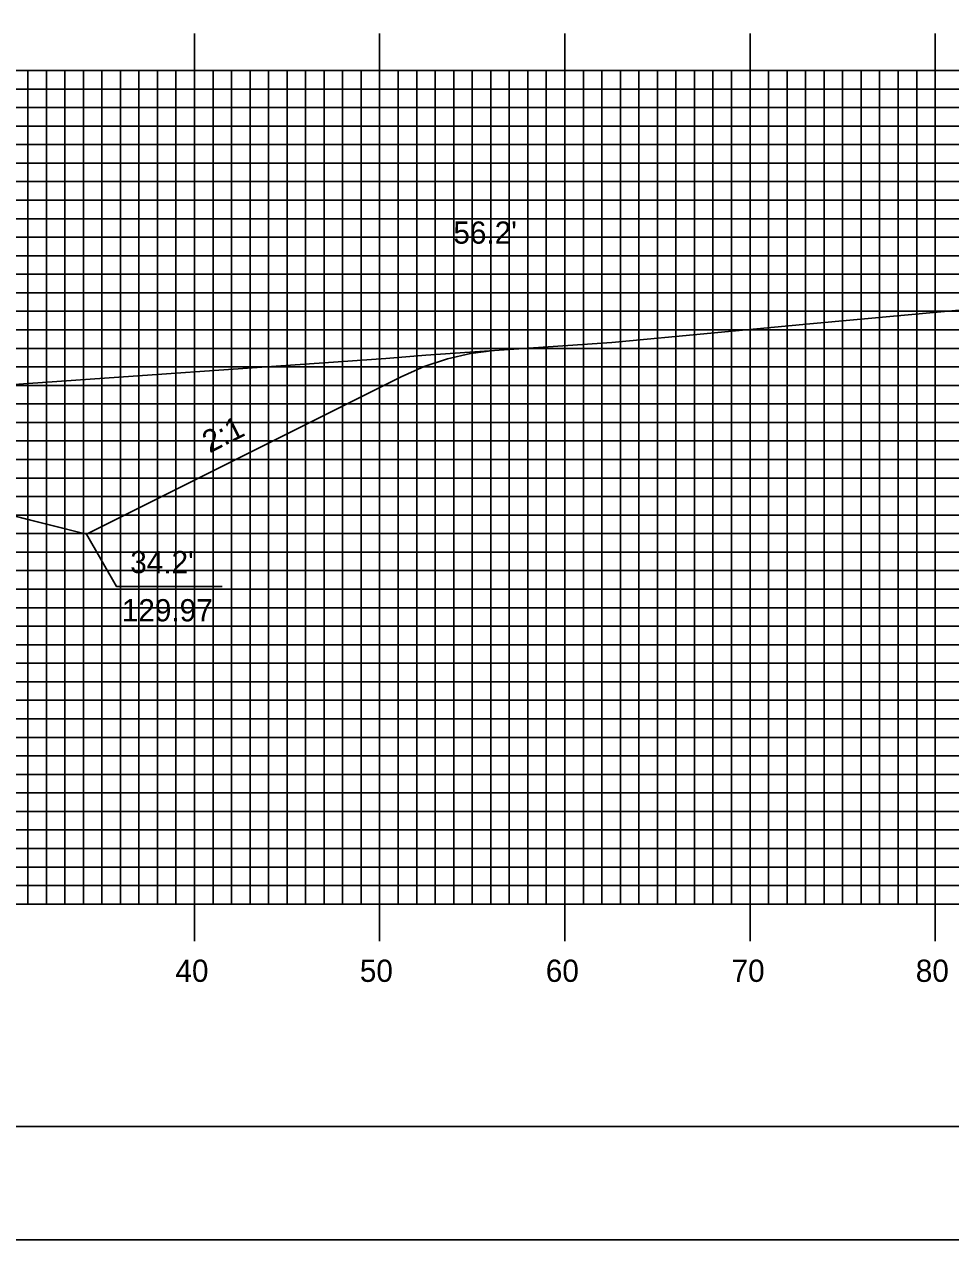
# Model space of a CAD drawing. Extents: x 1782647 to 1782990, y 442591 to 442811.
# Drawn here: x 1782843.8 to 1782893.8, y 442590.5 to 442656.2 of the extents above; entities that cross this region are included whole.
import ezdxf

# ---------------------------------------------------------------- set-up
doc = ezdxf.new("R2010")
doc.units = 0
for name, color, linetype in [('ANNOTATION', 7, 'Continuous'), ('BORDER', 7, 'Continuous'), ('D_Roadway_Centerline', 7, 'Continuous'), ('D_Roadway_SlopeLines', 7, 'Continuous'), ('D_Text_Standard', 7, 'Continuous'), ('H_V ANNOTATION', 7, 'Continuous'), ('MAJOR', 7, 'Continuous'), ('MINOR', 7, 'Continuous'), ('PLOT BOUNDARY', 7, 'Continuous'), ('S_Roadway_Centerline', 7, 'Continuous')]:
    doc.layers.add(name, color=color, linetype=linetype)

msp = doc.modelspace()

# ---------------------------------------------------------------- linework, layer by layer
at = {"layer": 'ANNOTATION'}
msp.add_lwpolyline([(1782854.435, 442625.801), (1782848.743, 442625.801), (1782847.121, 442628.634)], dxfattribs=at)
at = {"layer": 'BORDER'}
msp.add_lwpolyline([(1782663.347, 442596.665), (1782983.347, 442596.665), (1782983.347, 442806.665), (1782663.347, 442806.665)], close=True, dxfattribs=at)
at = {"layer": 'D_Roadway_Centerline'}
msp.add_lwpolyline([(1782771.185, 442630.8), (1782772.435, 442630.887), (1782773.685, 442630.771), (1782774.935, 442630.451), (1782776.185, 442629.928), (1782778.773, 442628.634), (1782782.773, 442629.634), (1782792.947, 442632.178), (1782800.947, 442632.498), (1782812.947, 442632.738), (1782824.947, 442632.498), (1782832.947, 442632.178), (1782843.121, 442629.634), (1782847.121, 442628.634), (1782864.105, 442637.126), (1782865.355, 442637.684), (1782866.605, 442638.106), (1782867.855, 442638.394), (1782869.105, 442638.546)], dxfattribs=at)
at = {"layer": 'D_Roadway_SlopeLines'}
for points in [[(1782847.121, 442628.634), (1782864.105, 442637.126), (1782865.355, 442637.684), (1782866.605, 442638.106), (1782867.855, 442638.394), (1782869.105, 442638.546)], [(1782832.947, 442632.178), (1782847.121, 442628.634)]]:
    msp.add_lwpolyline(points, dxfattribs=at)
at = {"layer": 'MAJOR'}
for p, q in [((1782852.947, 442655.669), (1782852.947, 442653.665)), ((1782862.947, 442655.669), (1782862.947, 442653.665)), ((1782872.947, 442655.669), (1782872.947, 442653.665)), ((1782882.947, 442655.669), (1782882.947, 442653.665)), ((1782892.947, 442655.669), (1782892.947, 442653.665)), ((1782672.947, 442653.665), (1782952.947, 442653.665)), ((1782672.947, 442653.665), (1782952.947, 442653.665)), ((1782852.947, 442608.665), (1782852.947, 442653.665)), ((1782862.947, 442608.665), (1782862.947, 442653.665)), ((1782872.947, 442608.665), (1782872.947, 442653.665)), ((1782882.947, 442608.665), (1782882.947, 442653.665)), ((1782892.947, 442608.665), (1782892.947, 442653.665)), ((1782672.947, 442648.665), (1782952.947, 442648.665)), ((1782672.947, 442643.665), (1782952.947, 442643.665)), ((1782672.947, 442638.665), (1782952.947, 442638.665)), ((1782672.947, 442633.665), (1782952.947, 442633.665)), ((1782672.947, 442628.665), (1782952.947, 442628.665)), ((1782672.947, 442623.665), (1782952.947, 442623.665)), ((1782672.947, 442618.665), (1782952.947, 442618.665)), ((1782672.947, 442613.665), (1782952.947, 442613.665)), ((1782672.947, 442608.665), (1782952.947, 442608.665)), ((1782672.947, 442608.665), (1782952.947, 442608.665)), ((1782852.947, 442606.661), (1782852.947, 442608.665)), ((1782862.947, 442606.661), (1782862.947, 442608.665)), ((1782872.947, 442606.661), (1782872.947, 442608.665)), ((1782882.947, 442606.661), (1782882.947, 442608.665)), ((1782892.947, 442606.661), (1782892.947, 442608.665))]:
    msp.add_line(p, q, dxfattribs=at)
at = {"layer": 'MINOR'}
for p, q in [((1782843.947, 442608.665), (1782843.947, 442653.665)), ((1782844.947, 442608.665), (1782844.947, 442653.665)), ((1782845.947, 442608.665), (1782845.947, 442653.665)), ((1782846.947, 442608.665), (1782846.947, 442653.665)), ((1782847.947, 442608.665), (1782847.947, 442653.665)), ((1782848.947, 442608.665), (1782848.947, 442653.665)), ((1782849.947, 442608.665), (1782849.947, 442653.665)), ((1782850.947, 442608.665), (1782850.947, 442653.665)), ((1782851.947, 442608.665), (1782851.947, 442653.665)), ((1782853.947, 442608.665), (1782853.947, 442653.665)), ((1782854.947, 442608.665), (1782854.947, 442653.665)), ((1782855.947, 442608.665), (1782855.947, 442653.665)), ((1782856.947, 442608.665), (1782856.947, 442653.665)), ((1782857.947, 442608.665), (1782857.947, 442653.665)), ((1782858.947, 442608.665), (1782858.947, 442653.665)), ((1782859.947, 442608.665), (1782859.947, 442653.665)), ((1782860.947, 442608.665), (1782860.947, 442653.665)), ((1782861.947, 442608.665), (1782861.947, 442653.665)), ((1782863.947, 442608.665), (1782863.947, 442653.665)), ((1782864.947, 442608.665), (1782864.947, 442653.665)), ((1782865.947, 442608.665), (1782865.947, 442653.665)), ((1782866.947, 442608.665), (1782866.947, 442653.665)), ((1782867.947, 442608.665), (1782867.947, 442653.665)), ((1782868.947, 442608.665), (1782868.947, 442653.665)), ((1782869.947, 442608.665), (1782869.947, 442653.665)), ((1782870.947, 442608.665), (1782870.947, 442653.665)), ((1782871.947, 442608.665), (1782871.947, 442653.665)), ((1782873.947, 442608.665), (1782873.947, 442653.665)), ((1782874.947, 442608.665), (1782874.947, 442653.665)), ((1782875.947, 442608.665), (1782875.947, 442653.665)), ((1782876.947, 442608.665), (1782876.947, 442653.665)), ((1782877.947, 442608.665), (1782877.947, 442653.665)), ((1782878.947, 442608.665), (1782878.947, 442653.665)), ((1782879.947, 442608.665), (1782879.947, 442653.665)), ((1782880.947, 442608.665), (1782880.947, 442653.665)), ((1782881.947, 442608.665), (1782881.947, 442653.665)), ((1782883.947, 442608.665), (1782883.947, 442653.665)), ((1782884.947, 442608.665), (1782884.947, 442653.665)), ((1782885.947, 442608.665), (1782885.947, 442653.665)), ((1782886.947, 442608.665), (1782886.947, 442653.665)), ((1782887.947, 442608.665), (1782887.947, 442653.665)), ((1782888.947, 442608.665), (1782888.947, 442653.665)), ((1782889.947, 442608.665), (1782889.947, 442653.665)), ((1782890.947, 442608.665), (1782890.947, 442653.665)), ((1782891.947, 442608.665), (1782891.947, 442653.665)), ((1782672.947, 442652.665), (1782952.947, 442652.665)), ((1782672.947, 442651.665), (1782952.947, 442651.665)), ((1782672.947, 442650.665), (1782952.947, 442650.665)), ((1782672.947, 442649.665), (1782952.947, 442649.665)), ((1782672.947, 442647.665), (1782952.947, 442647.665)), ((1782672.947, 442646.665), (1782952.947, 442646.665)), ((1782672.947, 442645.665), (1782952.947, 442645.665)), ((1782672.947, 442644.665), (1782952.947, 442644.665)), ((1782672.947, 442642.665), (1782952.947, 442642.665)), ((1782672.947, 442641.665), (1782952.947, 442641.665)), ((1782672.947, 442640.665), (1782952.947, 442640.665)), ((1782672.947, 442639.665), (1782952.947, 442639.665)), ((1782672.947, 442637.665), (1782952.947, 442637.665)), ((1782672.947, 442636.665), (1782952.947, 442636.665)), ((1782672.947, 442635.665), (1782952.947, 442635.665)), ((1782672.947, 442634.665), (1782952.947, 442634.665)), ((1782672.947, 442632.665), (1782952.947, 442632.665)), ((1782672.947, 442631.665), (1782952.947, 442631.665)), ((1782672.947, 442630.665), (1782952.947, 442630.665)), ((1782672.947, 442629.665), (1782952.947, 442629.665)), ((1782672.947, 442627.665), (1782952.947, 442627.665)), ((1782672.947, 442626.665), (1782952.947, 442626.665)), ((1782672.947, 442625.665), (1782952.947, 442625.665)), ((1782672.947, 442624.665), (1782952.947, 442624.665)), ((1782672.947, 442622.665), (1782952.947, 442622.665)), ((1782672.947, 442621.665), (1782952.947, 442621.665)), ((1782672.947, 442620.665), (1782952.947, 442620.665)), ((1782672.947, 442619.665), (1782952.947, 442619.665)), ((1782672.947, 442617.665), (1782952.947, 442617.665)), ((1782672.947, 442616.665), (1782952.947, 442616.665)), ((1782672.947, 442615.665), (1782952.947, 442615.665)), ((1782672.947, 442614.665), (1782952.947, 442614.665)), ((1782672.947, 442612.665), (1782952.947, 442612.665)), ((1782672.947, 442611.665), (1782952.947, 442611.665)), ((1782672.947, 442610.665), (1782952.947, 442610.665)), ((1782672.947, 442609.665), (1782952.947, 442609.665))]:
    msp.add_line(p, q, dxfattribs=at)
at = {"layer": 'PLOT BOUNDARY'}
msp.add_lwpolyline([(1782647.16, 442590.547), (1782987.16, 442590.547), (1782987.16, 442810.547), (1782647.16, 442810.547)], close=True, dxfattribs=at)
at = {"layer": 'S_Roadway_Centerline'}
msp.add_lwpolyline([(1782759.409, 442628.584), (1782769.904, 442630.592), (1782771.644, 442630.875), (1782773.198, 442631.131), (1782791.798, 442632.903), (1782797.041, 442633.325), (1782806.857, 442633.739), (1782816.845, 442634.722), (1782817.791, 442634.815), (1782818.812, 442634.918), (1782829.734, 442635.795), (1782841.885, 442636.625), (1782842.013, 442636.634), (1782842.143, 442636.643), (1782863.277, 442638.125), (1782865.446, 442638.297), (1782875.481, 442638.98), (1782886.179, 442639.988), (1782898.169, 442641.087)], dxfattribs=at)

# ---------------------------------------------------------------- texts
at = {"layer": 'ANNOTATION'}
msp.add_text('2:1', height=1.2, rotation=26.56505, dxfattribs=at).set_placement((1782853.758, 442632.989))
for s, p in [("34.2'", (1782849.478, 442626.527)), ('129.97', (1782849.023, 442623.927))]:
    msp.add_text(s, height=1.2, dxfattribs=at).set_placement(p)
at = {"layer": 'D_Text_Standard'}
msp.add_text("56.2'", height=1.2, dxfattribs=at).set_placement((1782866.927, 442644.315))
at = {"layer": 'H_V ANNOTATION'}
for s, p in [('40', (1782851.919, 442604.465)), ('50', (1782861.876, 442604.465)), ('60', (1782871.919, 442604.465)), ('70', (1782881.951, 442604.465)), ('80', (1782891.898, 442604.465))]:
    msp.add_text(s, height=1.2, dxfattribs=at).set_placement(p)

doc.saveas('drawing.dxf')
